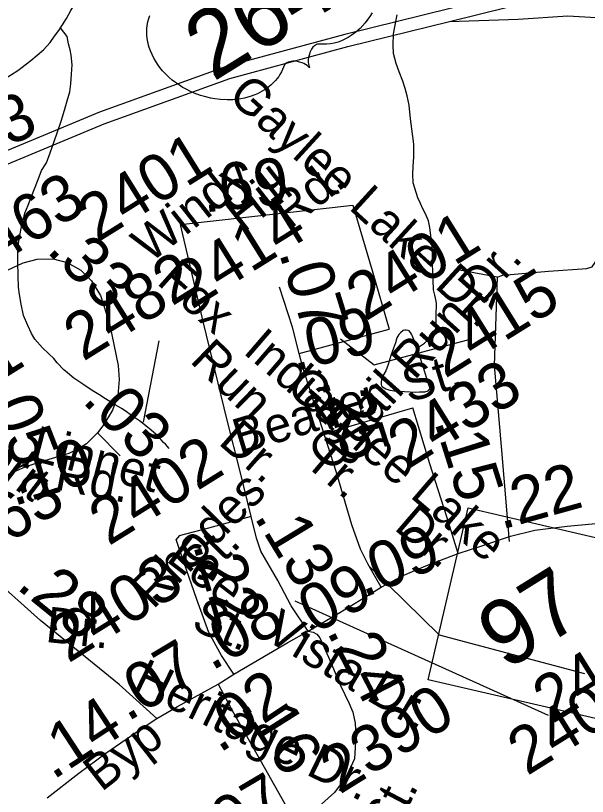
# Model space of a CAD drawing. Extents: x 2001466 to 31450019, y -30647475 to 847247.
# Drawn here: x 2181740 to 2184794, y 751246 to 755417 of the extents above; entities that cross this region are included whole.
import ezdxf

# ---------------------------------------------------------------- set-up
doc = ezdxf.new("R2010")
doc.units = 0
for name, color, linetype in [('Exist Hydrographic Misc Water Feature', 7, 'Continuous'), ('Exist Road Non-System Type 51', 7, 'Continuous'), ('Exist Road Non-System Type 51 Label', 7, 'Continuous'), ('Exist Road Primary Interstate Ramp 1 Lane Attributed', 7, 'Continuous'), ('Exist Road Primary NC Attributed', 7, 'Continuous'), ('Exist Road Primary NC Label', 7, 'Continuous'), ('Exist Road Primary NC Service Mileage Hundredths English Label', 7, 'Continuous'), ('Exist Road Primary NC Shield CELL', 7, 'Continuous'), ('Exist Road Primary NC Shield Number Label', 7, 'Continuous'), ('Exist Road Primary US Divided Attributed', 7, 'Continuous'), ('Exist Road Primary US Mileage Hundredths English Label', 7, 'Continuous'), ('Exist Road Primary US Shield CELL', 7, 'Continuous'), ('Exist Road Primary US Shield Number Label', 7, 'Continuous'), ('Exist Road Secondary Mileage Hundredths English Label', 7, 'Continuous'), ('Exist Road Secondary Type 51 Attributed', 7, 'Continuous'), ('Exist Road Secondary Type 51 Label', 7, 'Continuous'), ('Exist Road Secondary Type 51 Number Label', 7, 'Continuous')]:
    doc.layers.add(name, color=color, linetype=linetype)

msp = doc.modelspace()

# ---------------------------------------------------------------- linework, layer by layer
at = {"layer": 'Exist Hydrographic Misc Water Feature'}
for points in [[(2181980.5, 755351), (2181990, 755367), (2182012.3, 755401), (2182035.9, 755443.2), (2182067.3, 755497.3), (2182089.2, 755531.3), (2182119, 755567.8), (2182140.9, 755592), (2182158.9, 755608), (2182206.7, 755642.1), (2182240.6, 755664.2), (2182282.2, 755694.4), (2182326.3, 755724.7), (2182351.9, 755739), (2182377.9, 755755), (2182405.8, 755773.5), (2182427.8, 755791.3)], [(2183885.3, 753640.5), (2183897.2, 753648.4), (2183925.3, 753666.5), (2183943.1, 753682.4), (2183962.8, 753702.6), (2183976.9, 753718.7), (2183980.8, 753724.6), (2183982.9, 753736.9), (2183986.4, 753758.6), (2183986.8, 753780.9), (2183986.2, 753802.9), (2183986.2, 753830.9), (2183988, 753862.7), (2183987.8, 753878.9), (2183986, 753890.5), (2183979.8, 753922.7), (2183973.2, 753952.5), (2183971.8, 753966.5), (2183971, 753992.6), (2183968.9, 754038.7), (2183966.7, 754098.7), (2183966.5, 754148.7), (2183964, 754200.5), (2183957.5, 754240.5), (2183953.8, 754284.4), (2183945.8, 754320.5), (2183929.2, 754358.4), (2183915, 754384), (2183902.7, 754412.2), (2183889, 754443.9), (2183863.9, 754523.9), (2183862.3, 754569.7), (2183863.9, 754610), (2183867.4, 754661.8), (2183867.2, 754729.9), (2183856.8, 754811.8), (2183850.4, 754865.6), (2183841.8, 754937.4), (2183832, 754987.6), (2183821.5, 755027.3), (2183809.2, 755067.3), (2183789.1, 755115.4), (2183772.9, 755161.2), (2183758.6, 755214.9), (2183756.5, 755259), (2183759.6, 755319), (2183769.4, 755375.1), (2183779.3, 755421.1)], [(2181660.3, 755073.2), (2181684, 755081.4), (2181718.1, 755101.4), (2181751.9, 755123.9), (2181821.4, 755176.3), (2181888.9, 755234.6), (2181924.6, 755272.6), (2181948.6, 755306.7), (2181970.5, 755337.1), (2181980.5, 755351)], [(2182560.6, 753104.8), (2182540.5, 753126.9), (2182530.7, 753136.9), (2182518.6, 753150.6), (2182490.5, 753178.7), (2182464.3, 753202.5), (2182436, 753224.3), (2182401.9, 753252.1), (2182369.9, 753274), (2182351.5, 753285.7), (2182331.8, 753299.6), (2182309.2, 753315.6), (2182263.3, 753343.3), (2182221.3, 753369.1), (2182185.2, 753392.8), (2182148.9, 753414.5), (2182098.9, 753448.4), (2182050.7, 753480.1), (2182017, 753507.9), (2181998.4, 753523.7), (2181962.3, 753561.6), (2181944, 753585.4), (2181917.8, 753609.3), (2181884.2, 753641.1), (2181843.6, 753688.6), (2181825.5, 753718.5), (2181805.4, 753760.5), (2181782.9, 753814.6), (2181770.8, 753874.4), (2181760.3, 753926.3), (2181756.4, 753966.3), (2181753.6, 754026.3), (2181751.5, 754100.1), (2181752.9, 754178.1), (2181762.8, 754242), (2181772, 754288), (2181780, 754320.1), (2181790.1, 754360.4), (2181807.7, 754404.4), (2181837.2, 754482.6), (2181861, 754540.7), (2181878.2, 754588.8), (2181904.5, 754630.7), (2181924.2, 754682.9), (2181945.5, 754744.9), (2181963.5, 754794.9), (2181983, 754853.3), (2182000.8, 754911.4), (2182016.4, 754961.4), (2182030.4, 755009.2), (2182036.1, 755051.3), (2182039.6, 755103.5), (2182041.6, 755153.5), (2182036.9, 755205.3), (2182031, 755233.4), (2182022.8, 755265.1), (2182016.2, 755305.4), (2181980.5, 755351)], [(2183885.3, 753640.5), (2183871.1, 753678.3), (2183858.6, 753708.2), (2183854.5, 753714.1), (2183849, 753723.8), (2183842.6, 753732.1), (2183836.5, 753733.8), (2183826.8, 753736.1), (2183818.6, 753735.7), (2183810.6, 753733.7), (2183796.7, 753721.6), (2183786.8, 753713.7), (2183777.2, 753695.7), (2183768.8, 753669.4), (2183759.2, 753639.7), (2183745.2, 753601.6), (2183730, 753553.6), (2183718, 753519.3), (2183700.1, 753489.2), (2183694.2, 753475.5), (2183692.1, 753453.5), (2183692.7, 753449.3), (2183692.5, 753445.3), (2183694.4, 753439.3), (2183700.7, 753433.5), (2183718.6, 753423.5), (2183738.5, 753415.6), (2183752.2, 753413.5), (2183772.5, 753409.7), (2183816.8, 753407.9), (2183876.5, 753404.5), (2183898.6, 753406.5), (2183926.5, 753406.7), (2183944.5, 753412.5), (2183954.6, 753424.7), (2183946.4, 753448.7), (2183936.5, 753478.6), (2183919.9, 753534.7), (2183903.5, 753584.6), (2183889, 753630.2), (2183885.3, 753640.5)]]:
    msp.add_lwpolyline(points, dxfattribs=at)
at = {"layer": 'Exist Road Non-System Type 51'}
for p, q in [((2184313.2, 754020), (2184112, 754056.4)), ((2183404.5, 753188.5), (2183862.3, 753320.8)), ((2184333.3, 753115.3), (2184376.9, 752607.5))]:
    msp.add_line(p, q, dxfattribs=at)
for points in [[(2184313.2, 754020), (2184342.3, 754029.7), (2184587.1, 754051.5), (2184790.7, 754066.1), (2184819.8, 754074.6), (2184848.9, 754115.8), (2184868.3, 754193.4), (2184870.7, 754467.4), (2184870.7, 755095.5), (2184879.6, 755138.5)], [(2184313.2, 754020), (2184296.2, 753547.1), (2184333.3, 753115.3)]]:
    msp.add_lwpolyline(points, dxfattribs=at)
at = {"layer": 'Exist Road Primary Interstate Ramp 1 Lane Attributed'}
msp.add_lwpolyline([(2184057.3, 755385.1), (2184425.6, 755398.2), (2184689.3, 755416.1), (2184902.1, 755403.5), (2185144.9, 755378.3), (2185286.2, 755356.4)], dxfattribs=at)
at = {"layer": 'Exist Road Primary NC Attributed'}
for points in [[(2184105.1, 752542.7), (2184236.4, 752586.7), (2184383.9, 752634.9), (2184513.2, 752668.4), (2184686.9, 752689.3), (2184897.2, 752708.2), (2185123.7, 752731.2), (2185191.7, 752731.2), (2185310, 752739.6)], [(2183693.3, 752362.6), (2183810, 752425.5), (2183931.4, 752476.8), (2184105.1, 752542.7)], [(2183303.7, 752128.8), (2183462.6, 752222.3), (2183586.6, 752297.7), (2183693.3, 752362.6)], [(2182905.9, 751898.8), (2183195.2, 752067.3), (2183303.7, 752128.8)], [(2182822.2, 751845.4), (2182905.9, 751898.8)], [(2182495.2, 751662.1), (2182605.1, 751724.9), (2182822.2, 751845.4)], [(2181909.2, 751237), (2182077.2, 751368.9), (2182222.6, 751476.8), (2182410.4, 751606.6), (2182495.2, 751662.1)]]:
    msp.add_lwpolyline(points, dxfattribs=at)
at = {"layer": 'Exist Road Primary NC Shield CELL'}
msp.add_lwpolyline([(2183944.4, 751868.9), (2184157.6, 752786.3), (2185075, 752573.1), (2184861.8, 751655.7)], close=True, dxfattribs=at)
at = {"layer": 'Exist Road Primary US Divided Attributed'}
for points in [[(2184057.3, 755385.1), (2184367.1, 755462), (2185127.3, 755612.3), (2185311.3, 755656.2)], [(2184342.9, 755525.5), (2183498.3, 755316.3), (2182865.1, 755145.4), (2182188.8, 754901.6), (2181651.7, 754678.1), (2180897.2, 754312.8), (2179857.2, 753755.9), (2179289.5, 753460.8), (2178493.6, 753035.9), (2178148.4, 752839.7), (2177995.1, 752736.9)], [(2177992.8, 752657.4), (2178181.8, 752781.1), (2178526.2, 752976.8), (2179320.9, 753401.2), (2179888.6, 753696.2), (2180927.8, 754252.7), (2181679.4, 754616.6), (2182213.2, 754838.8), (2182885.3, 755081), (2183515.2, 755251), (2184057.3, 755385.1)]]:
    msp.add_lwpolyline(points, dxfattribs=at)
at = {"layer": 'Exist Road Primary US Shield CELL'}
msp.add_lwpolyline([(2183644.4, 755431.7), (2183632.9, 755412.6), (2183622, 755396.8), (2183607.2, 755377.4), (2183580.5, 755348.4), (2183570.3, 755338.7), (2183557.7, 755327.9), (2183545.5, 755318.5), (2183533.3, 755309.9), (2183516.3, 755299.3), (2183498.6, 755290.1), (2183481.2, 755282.4), (2183462.4, 755275.5), (2183441.7, 755269.9), (2183422.1, 755266.2), (2183401.2, 755264.1), (2183363.6, 755264.3), (2183353.2, 755263.6), (2183348.1, 755262), (2183337.3, 755256), (2183328.8, 755247.9), (2183321.3, 755237.6), (2183317.2, 755230.6), (2183312.5, 755220.3), (2183309.3, 755211.5), (2183306.3, 755199.8), (2183304.8, 755190.6), (2183303.8, 755183.6), (2183303.6, 755166.8), (2183304.5, 755159.5), (2183306.2, 755150.3), (2183310.4, 755138), (2183298.5, 755149.5), (2183288.9, 755156), (2183279.4, 755160.9), (2183270.3, 755164.7), (2183257.2, 755168.7), (2183246.3, 755171), (2183233.9, 755172.6), (2183221.8, 755172.4), (2183212.5, 755171.7), (2183204.6, 755170.1), (2183195.5, 755167.2), (2183188.7, 755163.7), (2183183.5, 755160.2), (2183177.3, 755154), (2183171.8, 755140.8), (2183166.5, 755128.5), (2183160.3, 755115.8), (2183152.2, 755101.8), (2183145.8, 755092.2), (2183137.8, 755081.5), (2183128, 755069.6), (2183116.8, 755057.8), (2183104.7, 755046.5), (2183093.8, 755037), (2183081.5, 755027.7), (2183070, 755020), (2183057.7, 755012.5), (2183045.6, 755006.3), (2183031.6, 754999.2), (2183013.6, 754991.4), (2182998, 754985.9), (2182981.1, 754980.8), (2182963.4, 754976.2), (2182943.8, 754972.4), (2182918.6, 754968.7), (2182900.3, 754967.2), (2182870.8, 754966.1), (2182834.2, 754967.9), (2182805.2, 754971.5), (2182783.2, 754975.5), (2182749.2, 754983.7), (2182728.4, 754989.9), (2182693.9, 755002.8), (2182670.4, 755013.1), (2182654.3, 755021.3), (2182629.5, 755035.2), (2182614.9, 755044.5), (2182594.6, 755058.7), (2182577.1, 755072.3), (2182561.2, 755085.7), (2182551.6, 755094.6), (2182535.9, 755110.8), (2182525.1, 755122.5), (2182511.3, 755139.2), (2182498, 755157.5), (2182486.7, 755175), (2182478, 755190), (2182469, 755208.2), (2182460.6, 755228.2), (2182454.3, 755246), (2182450.5, 755259.2), (2182446.6, 755275.8), (2182443.3, 755294.7), (2182441.5, 755313.6), (2182441, 755329.9), (2182441.6, 755348.2), (2182443.3, 755364.5), (2182446.9, 755383.5), (2182451.5, 755401.8), (2182456.8, 755417.1)], dxfattribs=at)
at = {"layer": 'Exist Road Secondary Type 51 Attributed'}
msp.add_line((2183255.7, 753611.2), (2183735.7, 753741.7), dxfattribs=at)
for points in [[(2182998, 752740.7), (2182939.4, 752981.5), (2182870.3, 753255.8), (2182743.7, 753775.2), (2182621.3, 754300.9), (2183542.1, 754403.5), (2183645.7, 754055.8), (2183735.7, 753741.7)], [(2180789.4, 753427), (2180876.1, 753603.1), (2180901.2, 753641.4), (2180931.4, 753678.1), (2180968.8, 753711.3), (2181004.9, 753735), (2181780.2, 754095.8), (2181856, 754115.8), (2181941.1, 754117.1), (2182015.5, 754098.5), (2182089.3, 754056.2), (2182146.5, 753999.1), (2182194.3, 753920.7), (2182242.2, 753771.9), (2182288.5, 753547.9), (2182293.8, 753472.2), (2182285.8, 753387.2), (2182258, 753308), (2182211.5, 753232.3), (2182176.9, 753187.1)], [(2183255.7, 753611.2), (2183218.8, 753752.2), (2183149.7, 753965.8)], [(2183693.3, 752362.6), (2183621.6, 752487.2), (2183581.9, 752566.8), (2183535.8, 752696.7), (2183452.1, 752981.5), (2183275.3, 753536.5), (2183255.7, 753611.2)], [(2184105.1, 752542.7), (2184044.4, 752738.6), (2183952.3, 753021.3), (2183862.3, 753320.8)], [(2182176.9, 753187.1), (2182118.4, 753129), (2182072.2, 753099.7), (2182024.1, 753078.2), (2181917.4, 753045), (2181799.1, 753007.3), (2181732.2, 752979.9), (2181692.7, 752961.6)], [(2182176.9, 753187.1), (2182299.2, 753064.9)], [(2182998, 752740.7), (2182769.9, 752678.9), (2182614, 752637), (2182597.2, 752618.1)], [(2183303.7, 752128.8), (2183212, 752263.2), (2183140.8, 752398.2), (2183050.3, 752555.3), (2183027.3, 752624.4), (2182998, 752740.7)], [(2182905.9, 751898.8), (2182840, 751998.2), (2182773, 752120.8), (2182707.6, 752296.7), (2182639.6, 752496.7), (2182597.2, 752618.1)], [(2182495.2, 751662.1), (2182293.2, 751843.3), (2181872.6, 752184.6), (2181580.7, 752444.3), (2181425.8, 752538.6), (2181342.9, 752573.4)], [(2183303.7, 752128.8), (2183329.1, 752122.7), (2183349.4, 752111.6), (2183364.7, 752092.2), (2183418.3, 751973.8), (2183476.2, 751838.1), (2183522.7, 751742), (2183540.8, 751696.1), (2183554.7, 751636.8), (2183557.5, 751568.4), (2183551.3, 751446.9), (2183506.3, 751350.6), (2183443.5, 751266.8), (2183357.7, 751189.3), (2183234.2, 751107.7)], [(2182822.2, 751845.4), (2182903.6, 751691.9), (2183068.9, 751400.8), (2183234.2, 751107.7)]]:
    msp.add_lwpolyline(points, dxfattribs=at)
at = {"layer": 'Exist Road Secondary Type 51 Number Label'}
for p, q in [((2182424, 753244.2), (2182507.6, 753679.1)), ((2183232.6, 752289.7), (2184584.6, 751679.6))]:
    msp.add_line(p, q, dxfattribs=at)
for points in [[(2183475.3, 753690.3), (2183655.6, 753551.6), (2184175.6, 753690.3)], [(2183634.8, 752470), (2184002.2, 752109.5), (2184778.8, 751901.5)]]:
    msp.add_lwpolyline(points, dxfattribs=at)

# ---------------------------------------------------------------- texts
at = {"layer": 'Exist Road Non-System Type 51 Label'}
msp.add_text('Beaver  St.', height=190, rotation=17.0696, dxfattribs=at).set_placement((2182935.9, 753070.8))
at = {"layer": 'Exist Road Primary NC Label'}
msp.add_text('Byp', height=190, rotation=38.0639, dxfattribs=at).set_placement((2182198.8, 751266.3))
at = {"layer": 'Exist Road Primary NC Service Mileage Hundredths English Label'}
for s, rotation, p in [('.22', 15.53, (2184334.5, 752669.9)), ('.09', 22.2906, (2183598.4, 752304.2)), ('.09', 28.0628, (2183256.1, 752068.6)), ('.08', 29.658, (2182787.3, 751913.3)), ('.07', 30.9574, (2182337.9, 751642)), ('.02', 33.5805, (2182829, 751473.3)), ('.14', 33.2601, (2181940.1, 751330.6))]:
    msp.add_text(s, height=250, rotation=rotation, dxfattribs=at).set_placement(p)
at = {"layer": 'Exist Road Primary NC Shield Number Label'}
msp.add_text('97', height=350, rotation=31.918, dxfattribs=at).set_placement((2184356.9, 751914.5))
at = {"layer": 'Exist Road Primary US Mileage Hundredths English Label'}
msp.add_text('1.53', height=250, rotation=24.2257, dxfattribs=at).set_placement((2181278.9, 754527.4))
at = {"layer": 'Exist Road Primary US Shield Number Label'}
msp.add_text('264', height=360, rotation=31.918, dxfattribs=at).set_placement((2182795.2, 755060.8))
at = {"layer": 'Exist Road Secondary Mileage Hundredths English Label'}
for s, rotation, p in [('.69', 6.2006, (2182746.2, 754364.2)), ('.33', 315.014, (2181899.9, 754156.9)), ('.07', 287.3048, (2183145.9, 754149.3)), ('.09', 14.0194, (2183230.2, 753514.9)), ('.03', 315.0142, (2182090.1, 753354.1)), ('.25', 287.6838, (2183367.1, 753462.1)), ('.05', 291.3573, (2181577.9, 753421.7)), ('.15', 287.4496, (2183975.1, 753247)), ('.10', 17.2759, (2181729.2, 752794.6)), ('.13', 301.2529, (2183010.6, 752739.3)), ('.22', 286.8148, (2182685.9, 752589.5)), ('.28', 320.9102, (2181738, 752360)), ('.24', 297.3421, (2183399.7, 752127.3)), ('.16', 302.1923, (2182935.7, 751730)), ('.07', 30.5626, (2182803, 750931.7))]:
    msp.add_text(s, height=250, rotation=rotation, dxfattribs=at).set_placement(p)
at = {"layer": 'Exist Road Secondary Type 51 Label'}
for s, rotation, p in [('Gaylee Lake Dr.', 317.5697, (2182868.2, 754978.3)), ('Windy', 38.1186, (2182457.8, 754090.2)), ('Hill', 38.1186, (2182953.6, 754250.8)), ('Rd.', 38.1186, (2183203.6, 754270.4)), ('Quail Run Dr.', 48.1102, (2183427.7, 752970.2)), ('Fox', 318.4063, (2182488.3, 753987.7)), ('Indian', 319.2228, (2182949.4, 753617)), ('Run', 315.9485, (2182666.2, 753568.7)), ('Bowsprit', 322.5863, (2181056.8, 753406.4)), ('Gaylee Lake', 319.3676, (2183176.8, 753418)), ('Dr.', 318.6917, (2182817.7, 753131.5)), ('Linnet', 345.2952, (2181812.5, 753044.4)), ('Tr.', 319.6019, (2183273.9, 753024.3)), ('Rd.', 349.2852, (2181942.9, 752886.5)), ('Rhodes', 45.494, (2182475, 752241.2)), ('Dr.', 319.3676, (2183756.5, 752675.5)), ('Lee', 322.2332, (2182537.5, 752506.3)), (' St.', 45.494, (2182684.6, 752321)), (' St.', 336.6018, (2182607.1, 752168.9)), ('Dr.', 353.7593, (2181895.9, 752071.4)), ('Vista Dr.', 329.2602, (2183060.2, 752090.5)), ('Heritage Dr.', 334.1103, (2182357.6, 751815.4)), ('Ridge  St.', 62.3936, (2183379.2, 750311.3))]:
    msp.add_text(s, height=190, rotation=rotation, dxfattribs=at).set_placement(p)
at = {"layer": 'Exist Road Secondary Type 51 Number Label'}
for s, p in [('2401', (2182176.5, 754201.9)), ('2463', (2181498, 753989.8)), ('2414', (2182680.3, 753844.1)), ('2401', (2183609.1, 753781.3)), ('2482', (2182101.2, 753566.6)), ('2415', (2184033.8, 753475.5)), ('2481', (2181169.6, 753159.2)), ('2433', (2183831.4, 752988.4)), ('2402', (2182236.8, 752580.9)), ('2463', (2181387.7, 752398.4)), ('2403', (2182021.4, 751954.4)), ('2414', (2184607.1, 751631.1)), ('2401', (2184472.2, 751353)), ('2390', (2183471.2, 751253.5))]:
    msp.add_text(s, height=250, rotation=31.918, dxfattribs=at).set_placement(p)

doc.saveas('drawing.dxf')
